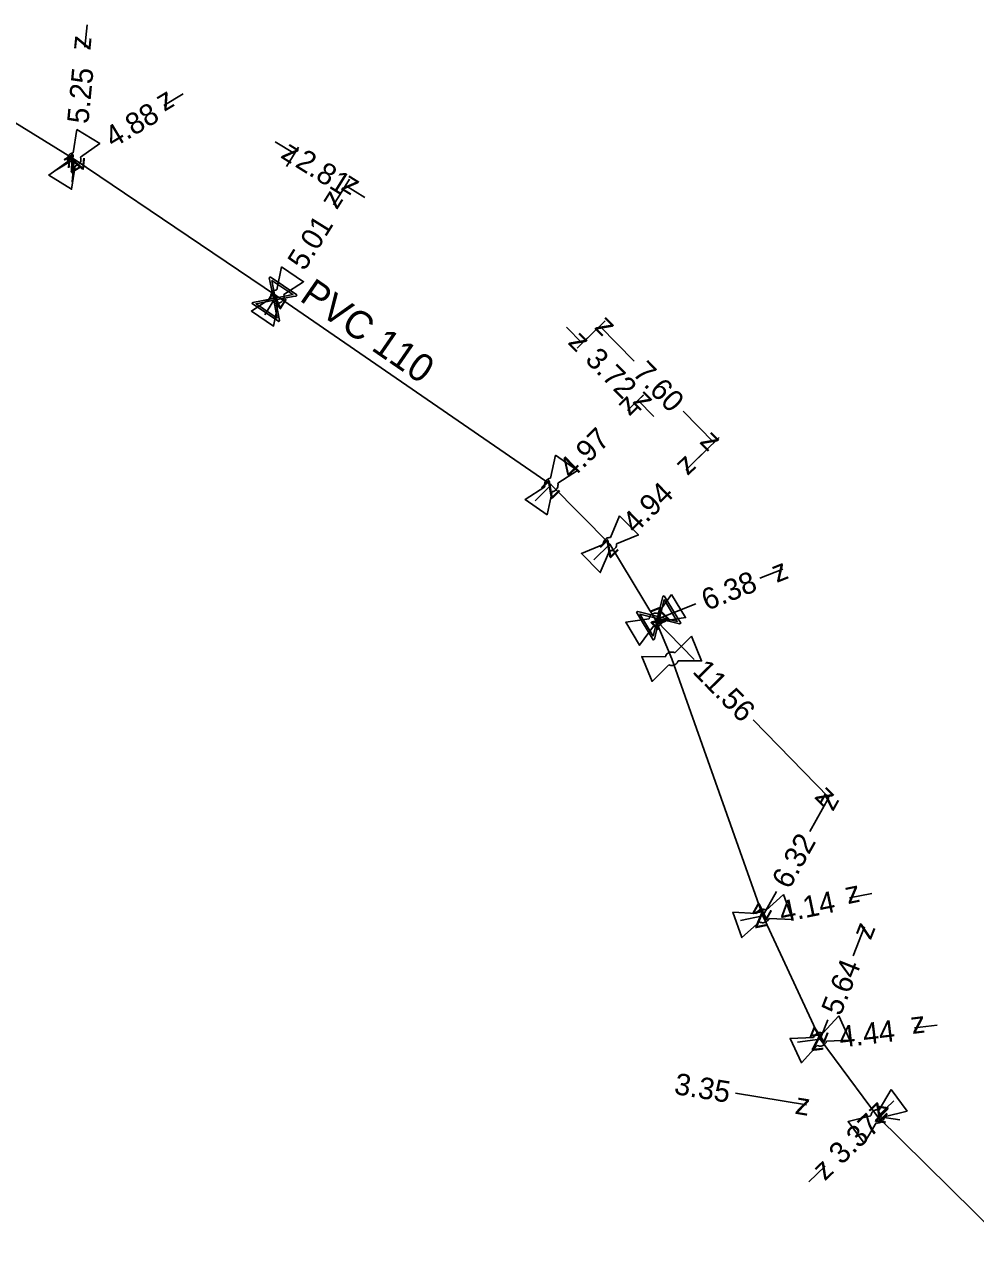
# Model space of a CAD drawing. Extents: x -638315 to -636370, y -1116147 to -1115110.
# Drawn here: x -637168.7 to -637124.5, y -1116023.5 to -1115965.9 of the extents above; entities that cross this region are included whole.
import ezdxf

# ---------------------------------------------------------------- set-up
doc = ezdxf.new("R2010")
doc.units = 0
for name, color, linetype in [('Default', 7, 'Continuous'), ('VP Kótování', 7, 'Continuous'), ('VP Lomový bod', 7, 'Continuous'), ('VP Přípojka', 7, 'Continuous'), ('VP Řad', 7, 'Continuous'), ('VP Řad - popis', 7, 'Continuous'), ('VP Šoupě', 7, 'Continuous')]:
    doc.layers.add(name, color=color, linetype=linetype)

msp = doc.modelspace()

# ---------------------------------------------------------------- linework, layer by layer
at = {"layer": 'Default'}
for points in [[(-637166.738, -1115972.255), (-637166.755, -1115972.204), (-637166.752, -1115972.15), (-637166.749, -1115972.066), (-637166.706, -1115971.996), (-637166.663, -1115971.926), (-637166.587, -1115971.885), (-637166.541, -1115971.859), (-637166.489, -1115971.851)], [(-637166.141, -1115972.066), (-637166.126, -1115972.115), (-637166.127, -1115972.169), (-637166.132, -1115972.255), (-637166.175, -1115972.325), (-637166.218, -1115972.394), (-637166.291, -1115972.435), (-637166.339, -1115972.461), (-637166.392, -1115972.469)], [(-637157.271, -1115978.632), (-637157.285, -1115978.581), (-637157.281, -1115978.527), (-637157.274, -1115978.443), (-637157.229, -1115978.375), (-637157.183, -1115978.307), (-637157.105, -1115978.269), (-637157.058, -1115978.244), (-637157.005, -1115978.239)], [(-637156.667, -1115978.467), (-637156.653, -1115978.518), (-637156.657, -1115978.571), (-637156.665, -1115978.657), (-637156.711, -1115978.725), (-637156.756, -1115978.793), (-637156.832, -1115978.83), (-637156.881, -1115978.855), (-637156.933, -1115978.86)], [(-637144.513, -1115987.419), (-637144.526, -1115987.368), (-637144.522, -1115987.314), (-637144.514, -1115987.23), (-637144.468, -1115987.162), (-637144.421, -1115987.095), (-637144.343, -1115987.057), (-637144.296, -1115987.033), (-637144.243, -1115987.028)], [(-637143.907, -1115987.26), (-637143.894, -1115987.31), (-637143.898, -1115987.364), (-637143.907, -1115987.45), (-637143.953, -1115987.517), (-637144, -1115987.584), (-637144.075, -1115987.621), (-637144.124, -1115987.645), (-637144.177, -1115987.65)], [(-637141.792, -1115990.121), (-637141.796, -1115990.069), (-637141.781, -1115990.016), (-637141.758, -1115989.935), (-637141.7, -1115989.877), (-637141.642, -1115989.82), (-637141.558, -1115989.797), (-637141.507, -1115989.783), (-637141.454, -1115989.787)], [(-637141.167, -1115990.078), (-637141.164, -1115990.13), (-637141.178, -1115990.182), (-637141.202, -1115990.264), (-637141.261, -1115990.322), (-637141.319, -1115990.379), (-637141.4, -1115990.401), (-637141.453, -1115990.416), (-637141.505, -1115990.411)], [(-637139.658, -1115993.578), (-637139.65, -1115993.526), (-637139.623, -1115993.479), (-637139.581, -1115993.405), (-637139.511, -1115993.363), (-637139.441, -1115993.321), (-637139.354, -1115993.318), (-637139.302, -1115993.316), (-637139.251, -1115993.333)], [(-637139.04, -1115993.683), (-637139.049, -1115993.734), (-637139.075, -1115993.781), (-637139.118, -1115993.856), (-637139.189, -1115993.898), (-637139.259, -1115993.94), (-637139.343, -1115993.943), (-637139.397, -1115993.944), (-637139.447, -1115993.927)], [(-637138.897, -1115995.343), (-637138.88, -1115995.292), (-637138.847, -1115995.249), (-637138.795, -1115995.183), (-637138.719, -1115995.152), (-637138.644, -1115995.12), (-637138.558, -1115995.131), (-637138.505, -1115995.137), (-637138.458, -1115995.161)], [(-637138.301, -1115995.539), (-637138.318, -1115995.588), (-637138.35, -1115995.63), (-637138.405, -1115995.698), (-637138.48, -1115995.729), (-637138.556, -1115995.76), (-637138.639, -1115995.75), (-637138.693, -1115995.743), (-637138.74, -1115995.719)], [(-637134.651, -1116007.316), (-637134.632, -1116007.267), (-637134.596, -1116007.226), (-637134.541, -1116007.162), (-637134.464, -1116007.135), (-637134.387, -1116007.108), (-637134.301, -1116007.123), (-637134.249, -1116007.132), (-637134.203, -1116007.158)], [(-637134.067, -1116007.544), (-637134.086, -1116007.592), (-637134.121, -1116007.633), (-637134.178, -1116007.697), (-637134.256, -1116007.724), (-637134.333, -1116007.752), (-637134.416, -1116007.737), (-637134.469, -1116007.727), (-637134.515, -1116007.701)], [(-637131.99, -1116013.095), (-637131.976, -1116013.044), (-637131.945, -1116013), (-637131.896, -1116012.931), (-637131.821, -1116012.897), (-637131.747, -1116012.862), (-637131.661, -1116012.869), (-637131.608, -1116012.873), (-637131.56, -1116012.895)], [(-637131.388, -1116013.266), (-637131.402, -1116013.316), (-637131.433, -1116013.36), (-637131.484, -1116013.429), (-637131.558, -1116013.464), (-637131.632, -1116013.498), (-637131.716, -1116013.491), (-637131.771, -1116013.487), (-637131.819, -1116013.465)], [(-637129.321, -1116016.748), (-637129.318, -1116016.695), (-637129.296, -1116016.645), (-637129.262, -1116016.568), (-637129.197, -1116016.519), (-637129.131, -1116016.471), (-637129.045, -1116016.46), (-637128.992, -1116016.452), (-637128.941, -1116016.464)], [(-637128.696, -1116016.792), (-637128.7, -1116016.844), (-637128.721, -1116016.893), (-637128.757, -1116016.971), (-637128.823, -1116017.02), (-637128.888, -1116017.069), (-637128.972, -1116017.08), (-637129.026, -1116017.087), (-637129.077, -1116017.075)]]:
    msp.add_open_spline(points, degree=3, dxfattribs=at)
at = {"layer": 'VP Kótování'}
for points in [[(-637165.84, -1115965.885), (-637165.94, -1115966.93)], [(-637161.36, -1115969.109), (-637162.26, -1115969.65)], [(-637157.07, -1115971.337), (-637156.18, -1115971.894)], [(-637167.34, -1115972.701), (-637166.44, -1115972.16)], [(-637166.54, -1115973.205), (-637166.44, -1115972.16)], [(-637156.555, -1115972.493), (-637155.995, -1115971.597)], [(-637154.17, -1115973.983), (-637153.61, -1115973.087)], [(-637153.799, -1115973.389), (-637154.355, -1115974.28)], [(-637152.904, -1115973.94), (-637153.795, -1115973.384)], [(-637157.563, -1115979.416), (-637157.007, -1115978.525)], [(-637143.506, -1115979.982), (-637142.772, -1115980.732)], [(-637143.01, -1115980.965), (-637141.702, -1115979.686)], [(-637140.354, -1115981.564), (-637141.952, -1115979.93)], [(-637143.01, -1115980.965), (-637142.522, -1115980.488)], [(-637139.909, -1115983.134), (-637140.66, -1115983.868)], [(-637140.41, -1115983.623), (-637139.922, -1115983.146)], [(-637139.438, -1115984.141), (-637140.172, -1115983.39)], [(-637138.072, -1115983.897), (-637136.638, -1115985.363)], [(-637137.696, -1115986.398), (-637136.388, -1115985.119)], [(-637137.195, -1115985.909), (-637137.946, -1115986.643)], [(-637144.961, -1115988.074), (-637144.21, -1115987.34)], [(-637142.231, -1115990.834), (-637141.48, -1115990.1)], [(-637134.493, -1115991.686), (-637133.43, -1115991.26)], [(-637137.472, -1115992.878), (-637139.35, -1115993.63)], [(-637137.558, -1115995.468), (-637139.35, -1115993.63)], [(-637134.808, -1115998.291), (-637131.28, -1116001.91)], [(-637132.161, -1116003.49), (-637131.28, -1116001.91)], [(-637133.725, -1116006.291), (-637134.36, -1116007.43)], [(-637129.282, -1116006.377), (-637130.31, -1116006.59)], [(-637135.388, -1116007.643), (-637134.36, -1116007.43)], [(-637130.147, -1116009.292), (-637129.61, -1116007.94)], [(-637131.33, -1116012.274), (-637131.69, -1116013.18)], [(-637126.238, -1116012.525), (-637127.28, -1116012.65)], [(-637132.732, -1116013.305), (-637131.69, -1116013.18)], [(-637135.622, -1116015.691), (-637132.32, -1116016.23)], [(-637128.251, -1116016.045), (-637129.01, -1116016.77)], [(-637127.974, -1116016.939), (-637129.01, -1116016.77)], [(-637132.209, -1116019.825), (-637131.45, -1116019.1)]]:
    msp.add_lwpolyline(points, dxfattribs=at)
at = {"layer": 'VP Lomový bod'}
for points in [[(-637166.489, -1115971.851), (-637166.314, -1115970.769)], [(-637166.314, -1115970.769), (-637165.251, -1115971.426), (-637166.141, -1115972.066)], [(-637166.392, -1115972.469), (-637166.566, -1115973.552), (-637167.629, -1115972.895), (-637166.738, -1115972.255)], [(-637157.005, -1115978.239), (-637156.789, -1115977.164)], [(-637156.789, -1115977.164), (-637155.752, -1115977.863), (-637156.667, -1115978.467)], [(-637156.933, -1115978.86), (-637157.151, -1115979.936), (-637158.187, -1115979.237), (-637157.271, -1115978.632)], [(-637144.243, -1115987.028), (-637144.016, -1115985.956)], [(-637144.016, -1115985.956), (-637142.987, -1115986.665), (-637143.907, -1115987.26)], [(-637144.177, -1115987.65), (-637144.405, -1115988.724), (-637145.434, -1115988.015), (-637144.513, -1115987.419)], [(-637141.454, -1115989.787), (-637141.031, -1115988.776)], [(-637141.031, -1115988.776), (-637140.152, -1115989.665), (-637141.167, -1115990.078)], [(-637141.505, -1115990.411), (-637141.929, -1115991.423), (-637142.808, -1115990.534), (-637141.792, -1115990.121)], [(-637139.251, -1115993.333), (-637138.603, -1115992.45)], [(-637138.603, -1115992.45), (-637137.957, -1115993.52), (-637139.04, -1115993.683)], [(-637139.447, -1115993.927), (-637140.097, -1115994.811), (-637140.743, -1115993.741), (-637139.658, -1115993.578)], [(-637138.458, -1115995.161), (-637137.684, -1115994.384)], [(-637137.684, -1115994.384), (-637137.206, -1115995.539), (-637138.301, -1115995.539)], [(-637138.74, -1115995.719), (-637139.515, -1115996.496), (-637139.994, -1115995.341), (-637138.897, -1115995.343)], [(-637134.203, -1116007.158), (-637133.39, -1116006.424)], [(-637133.39, -1116006.424), (-637132.973, -1116007.602), (-637134.067, -1116007.544)], [(-637134.515, -1116007.701), (-637135.33, -1116008.436), (-637135.747, -1116007.257), (-637134.651, -1116007.316)], [(-637131.56, -1116012.895), (-637130.819, -1116012.087)], [(-637130.819, -1116012.087), (-637130.293, -1116013.221), (-637131.388, -1116013.266)], [(-637131.819, -1116013.465), (-637132.56, -1116014.274), (-637133.087, -1116013.14), (-637131.99, -1116013.095)], [(-637128.941, -1116016.464), (-637128.382, -1116015.521)], [(-637128.382, -1116015.521), (-637127.634, -1116016.523), (-637128.696, -1116016.792)], [(-637129.077, -1116017.075), (-637129.637, -1116018.019), (-637130.385, -1116017.017), (-637129.321, -1116016.748)]]:
    msp.add_lwpolyline(points, dxfattribs=at)
at = {"layer": 'VP Přípojka'}
for points in [[(-637157.007, -1115978.525), (-637157.11, -1115978.68)], [(-637139.187, -1115993.514), (-637139.35, -1115993.63)]]:
    msp.add_lwpolyline(points, dxfattribs=at)
at = {"layer": 'VP Řad'}
msp.add_lwpolyline([(-637174.427, -1115967.22), (-637166.44, -1115972.16), (-637160.549, -1115976.135), (-637157.007, -1115978.525), (-637156.97, -1115978.55), (-637144.21, -1115987.34), (-637141.48, -1115990.1), (-637139.35, -1115993.63), (-637138.6, -1115995.44), (-637134.36, -1116007.43), (-637131.69, -1116013.18), (-637129.01, -1116016.77), (-637122.22, -1116023.48), (-637113.15, -1116022.73), (-637096.4, -1116022.3), (-637090.87, -1116022.36), (-637090.44, -1116022.36), (-637090.398, -1116022.36), (-637090.11, -1116022.496)], dxfattribs=at)
at = {"layer": 'VP Šoupě'}
for points in [[(-637157.312, -1115977.639), (-637156.069, -1115978.478), (-637156.106, -1115978.532), (-637156.233, -1115978.553), (-637157.057, -1115978.714), (-637156.871, -1115979.666), (-637156.908, -1115979.721), (-637158.151, -1115978.882), (-637158.115, -1115978.827), (-637157.16, -1115978.644), (-637157.322, -1115977.82), (-637157.349, -1115977.693), (-637157.312, -1115977.639)], [(-637157.234, -1115977.804), (-637157.074, -1115978.627), (-637156.253, -1115978.467), (-637157.234, -1115977.804)], [(-637156.982, -1115979.558), (-637157.144, -1115978.731), (-637157.969, -1115978.892), (-637156.982, -1115979.558)], [(-637138.956, -1115992.501), (-637138.181, -1115993.785), (-637138.237, -1115993.819), (-637138.361, -1115993.784), (-637139.177, -1115993.584), (-637139.409, -1115994.526), (-637139.465, -1115994.56), (-637140.24, -1115993.276), (-637140.184, -1115993.242), (-637139.241, -1115993.477), (-637139.04, -1115992.661), (-637139.012, -1115992.535), (-637138.956, -1115992.501)], [(-637138.955, -1115992.684), (-637139.155, -1115993.498), (-637138.343, -1115993.698), (-637138.955, -1115992.684)], [(-637139.463, -1115994.381), (-637139.262, -1115993.562), (-637140.079, -1115993.361), (-637139.463, -1115994.381)]]:
    msp.add_lwpolyline(points, dxfattribs=at)

# ---------------------------------------------------------------- texts
at = {"layer": 'VP Kótování'}
for s, rotation, p in [('z', 264.53899, (-637166.39, -1115966.385)), ('5.25', 84.53901, (-637165.782, -1115970.529)), ('z', 210.98393, (-637162.089, -1115968.964)), ('4.88', 30.9839, (-637164.627, -1115971.655)), ('z', 328.00541, (-637156.869, -1115972.053)), ('z', 30.9839, (-637166.611, -1115972.846)), ('z', 84.53901, (-637165.99, -1115972.705)), ('2.81', 328.00539, (-637156.196, -1115972.473)), ('z', 148.00543, (-637153.106, -1115973.224)), ('z', 238.00554, (-637154.514, -1115973.591)), ('5.01', 58.00556, (-637155.714, -1115977.399)), ('z', 58.00556, (-637156.848, -1115979.214)), ('z', 134.36559, (-637141.245, -1115979.938)), ('z', 314.36798, (-637143.479, -1115980.725)), ('3.72', 314.36802, (-637142.683, -1115981.538)), ('7.60', 314.36561, (-637140.467, -1115982.164)), ('z', 134.368, (-637139.465, -1115983.398)), ('z', 224.36359, (-637140.652, -1115983.161)), ('4.97', 44.36361, (-637143.268, -1115987.118)), ('z', 314.36557, (-637137.345, -1115985.356)), ('z', 224.36897, (-637137.938, -1115985.936)), ('z', 44.36361, (-637144.218, -1115988.047)), ('4.94', 44.36893, (-637140.304, -1115989.65)), ('z', 44.36893, (-637141.488, -1115990.807)), ('z', 21.81812, (-637133.708, -1115991.91)), ('6.38', 21.81812, (-637136.961, -1115993.212)), ('z', 201.8181, (-637139.072, -1115992.98)), ('z', 134.26412, (-637138.643, -1115993.639)), ('11.56', 314.26414, (-637137.672, -1115996.068)), ('z', 314.26416, (-637131.987, -1116001.901)), ('z', 60.83975, (-637131.087, -1116002.59)), ('6.32', 60.83975, (-637133.118, -1116006.229)), ('z', 191.71743, (-637129.922, -1116005.999)), ('4.14', 11.71745, (-637133.469, -1116007.756)), ('z', 240.83973, (-637134.553, -1116006.75)), ('z', 11.71745, (-637134.748, -1116008.021)), ('z', 68.34957, (-637129.33, -1116008.589)), ('5.64', 68.34957, (-637130.736, -1116012.133)), ('4.44', 6.85303, (-637130.742, -1116013.57)), ('z', 186.85301, (-637126.843, -1116012.094)), ('z', 248.34955, (-637131.97, -1116012.531)), ('z', 6.85303, (-637132.127, -1116013.736)), ('3.35', 350.73428, (-637138.525, -1116015.724)), ('z', 350.7343, (-637132.894, -1116016.643)), ('z', 223.67896, (-637128.994, -1116016.063)), ('z', 170.73426, (-637128.436, -1116016.357)), ('3.37', 43.67892, (-637130.69, -1116019.065)), ('z', 43.67892, (-637131.466, -1116019.807))]:
    msp.add_text(s, height=1, rotation=rotation, dxfattribs=at).set_placement(p)
at = {"layer": 'VP Řad - popis'}
msp.add_text('PVC 110', height=1.3, rotation=325.43814, dxfattribs=at).set_placement((-637155.99, -1115978.717))

doc.saveas('drawing.dxf')
